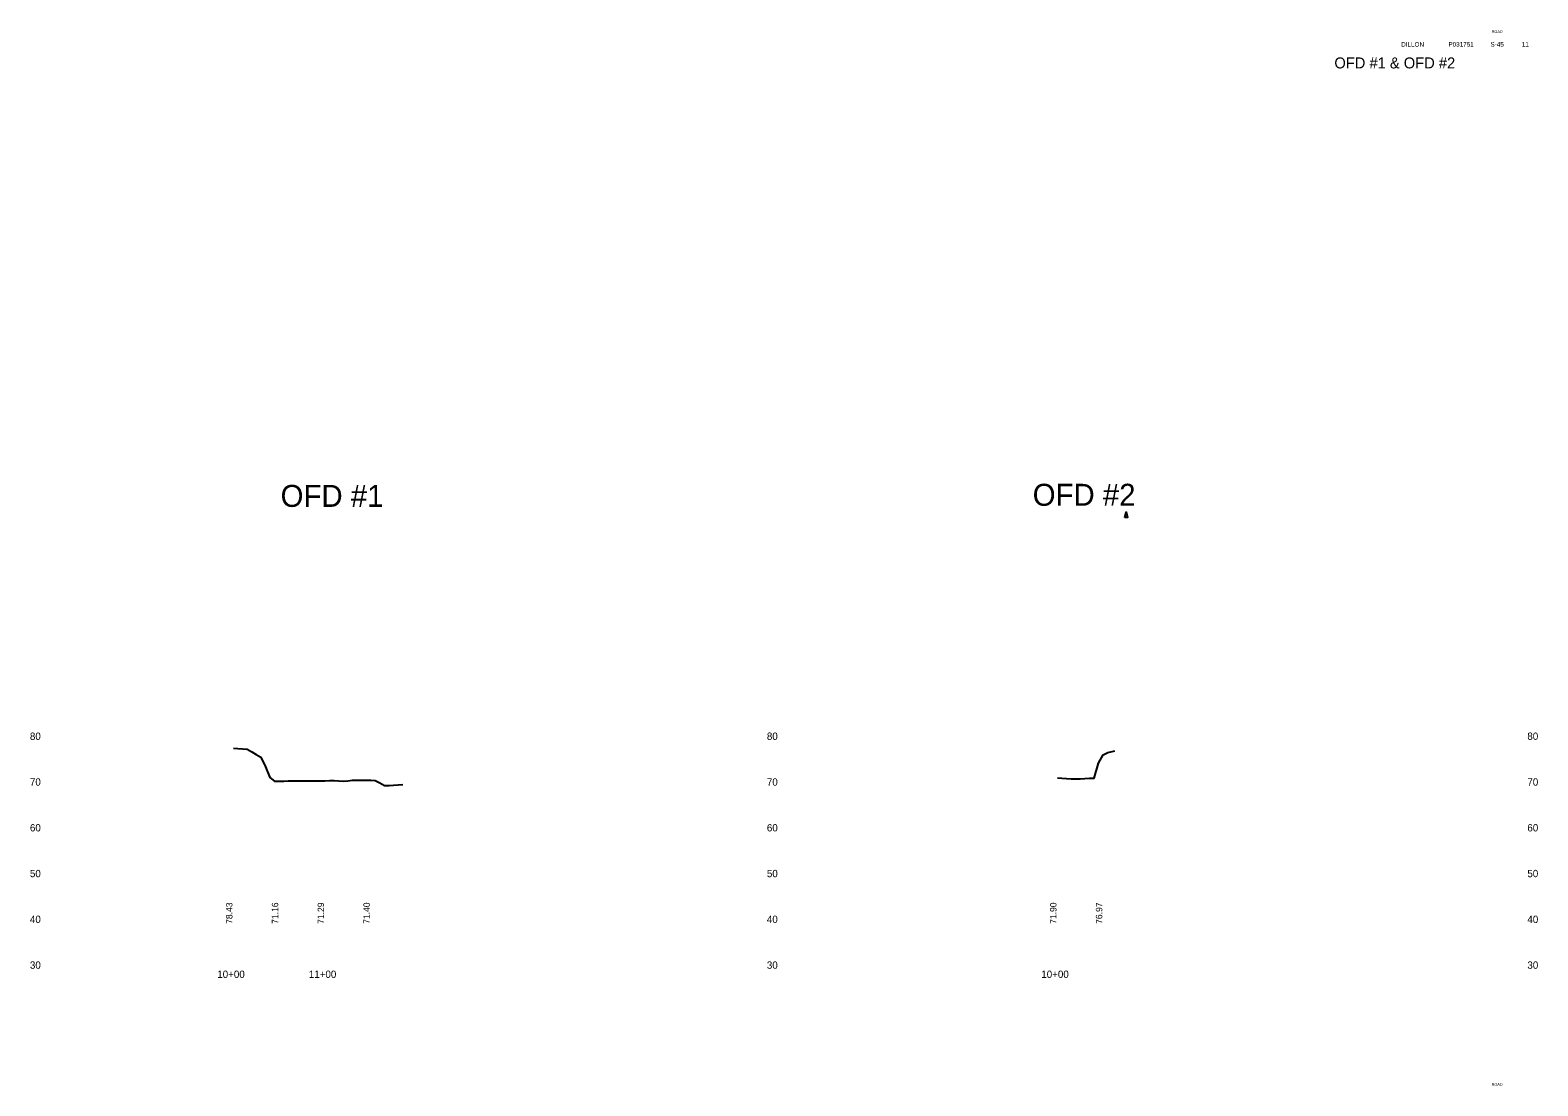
# Model space of a CAD drawing. Extents: x -3336 to 3318, y -3606 to 6276.
# Drawn here: x -72 to 1575, y 5123 to 6276 of the extents above; entities that cross this region are included whole.
import ezdxf

# ---------------------------------------------------------------- set-up
doc = ezdxf.new("R2010")
doc.units = 0
for name, color, linetype in [('RD_DDB_ElevTX', 7, 'Continuous'), ('RD_DDB_Profile_EX', 7, 'Continuous'), ('RD_DDB_StaTX', 7, 'Continuous'), ('RD_DDB_StripGrade', 7, 'Continuous'), ('RD_SHT_TX', 7, 'Continuous'), ('RD_TX_Drainage', 7, 'Continuous')]:
    doc.layers.add(name, color=color, linetype=linetype)

msp = doc.modelspace()

# ---------------------------------------------------------------- linework, layer by layer
at = {"layer": 'RD_DDB_Profile_EX'}
for points in [[(150, 5492.1), (155, 5491.7), (160, 5491.3), (165, 5490.8), (170, 5488), (175, 5485), (180, 5482), (185, 5471.4), (190, 5459.9), (195, 5455.8), (200, 5455.8), (205, 5455.9), (210, 5456.1), (215, 5456.1), (220, 5456.1), (225, 5456.1), (230, 5456.3), (235, 5456.4), (240, 5456.4), (245, 5456.4), (250, 5456.4), (255, 5456.6), (260, 5456.6), (265, 5456.2), (270, 5455.8), (275, 5456.1), (280, 5456.9), (285, 5457), (290, 5457), (295, 5456.9), (300, 5457), (305, 5456.8), (310, 5453.9), (315, 5451), (320, 5451.1), (325, 5451.4), (330, 5451.8), (335, 5452.1), (335.2, 5452.1)], [(1050, 5459.5), (1055, 5459.2), (1060, 5458.9), (1065, 5458.6), (1070, 5458.3), (1075, 5458.3), (1080, 5458.8), (1085, 5459.3), (1090, 5459), (1095, 5475.4), (1100, 5484.8), (1105, 5487.1), (1110, 5488.3), (1112.6, 5489)]]:
    msp.add_lwpolyline(points, dxfattribs=at)
at = {"layer": 'RD_TX_Drainage'}
msp.add_lwpolyline([(1123.5, 5744), (1125, 5750), (1126.5, 5744)], close=True, dxfattribs=at)

# ---------------------------------------------------------------- texts
at = {"layer": 'RD_DDB_ElevTX'}
for s, p in [('80', (-72.2, 5501)), ('80', (732.7, 5501)), ('80', (1563.3, 5501)), ('70', (-72.2, 5451)), ('70', (732.7, 5451)), ('70', (1563.3, 5451)), ('60', (-72.2, 5401)), ('60', (732.7, 5401)), ('60', (1563.3, 5401)), ('50', (-72.2, 5351)), ('50', (732.7, 5351)), ('50', (1563.3, 5351)), ('40', (-72.2, 5301)), ('40', (732.7, 5301)), ('40', (1563.3, 5301)), ('30', (-72.2, 5251)), ('30', (732.7, 5251)), ('30', (1563.3, 5251))]:
    msp.add_text(s, height=8, dxfattribs=at).set_placement(p)
at = {"layer": 'RD_DDB_StaTX'}
for s, p in [('10+00', (132.4, 5241)), ('11+00', (232.4, 5241)), ('10+00', (1032.4, 5241))]:
    msp.add_text(s, height=8, dxfattribs=at).set_placement(p)
at = {"layer": 'RD_DDB_StripGrade'}
for s, p in [('78.43', (149, 5300)), ('71.16', (199, 5300)), ('71.29', (249, 5300)), ('71.40', (299, 5300)), ('71.90', (1049, 5300)), ('76.97', (1099, 5300))]:
    msp.add_text(s, height=7, rotation=90, dxfattribs=at).set_placement(p)
at = {"layer": 'RD_SHT_TX'}
for s, height, p in [('ROAD', 3, (1524.3, 6273.1)), ('DILLON', 5, (1425.5, 6258.2)), ('P031751', 5, (1477.1, 6258.2)), ('S-45', 5, (1523, 6258.2)), ('11', 5, (1557.2, 6258.2)), ('OFD #1 & OFD #2', 12, (1352.5, 6234.4)), ('OFD #2', 24, (1023, 5756.7)), ('OFD #1 ', 24, (201.6, 5755.5)), ('ROAD', 3, (1524.3, 5123.1))]:
    msp.add_text(s, height=height, dxfattribs=at).set_placement(p)

doc.saveas('drawing.dxf')
